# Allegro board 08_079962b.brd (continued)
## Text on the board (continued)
Ref Des/Silkscreen Bottom: A | C | SECONDARY SIDE | 08-079962 REV B | BUCK-BOOST WITH iSHARE
User.Comments: HEATSINK | DETAIL B | DETAIL A | SEE NOTE 7 (4 PLACES) | DETAIL C | DETAIL D | WITH LEAD-FREE AND RoHS PCB ASSEMBLY STANDARDS | (EU RoHS DIRECTIVE 2002/95/EC). | 7.    INSTALL STANDOFF: M048748 (MFG PN: 8834) ON FOUR CORNER HOLES OF THE BOARD. | 8.    INSTALL RING LUG: M048369 (MFG PN: 8205), WASHER: M000140 (MFG PN:  98438A230), | 4.    RoHS COMPLIANCE NOTE: ASSEMBLY VENDOR SHOULD ASSURE COMPLIANCE | 5.    SMOOTHEN EDGES AND FREE FROM BURRS AFTER DEPANELIZATION PROCESS. | 6.    INSTALL SHUNT: M022926 (MFG PN: 2SN-BK-G) ON PIN 1 AND PIN 2 OF JP1. | SEE DETAIL B. | AND NUTS: M069690 (MFG PN: 92671A195) ON J1-J4. SEE DETAIL D.
Ref Des/Assembly Top: A | C
Ref Des/Silkscreen Top: A | C | 08-079962 REV B | PRIMARY SIDE | PARALLEL SYNCRONOUS | FEATURING GaN FETS | EVAL-LT8292-AZ | BUCK-BOOST WITH iSHARE | PARALLEL SYNCHRONOUS | FEATURING GaN FETs | EVAL-LT8292-GZ
PAGE_OUTLINE: FAB NOTES REVISION: 2ND NOVEMBER 2022 | 8.   IMPEDANCE REQUIREMENTS: IF NO STACKUP IS DEFINED, THE VENDOR IS ALLOWED TO ADJUST THE DIELECTRIC | 13.  PLATING SPECIFICATION: | 9.   FILLET OPTIONS TO ENHANCE RELIABILITY AT PAD JUNCTIONS WHERE SPACING PERMITS. | 10.  THIEVING: | 11.  LAYER TO LAYER REGISTRATION SHALL BE WITHIN 0.003 INCHES. | 12.  DRILL SIZES ARE FINISHED HOLE SIZES. ALL HOLES SHALL BE LOCATED WITHIN 0.005 INCHES DTP,UNLESS SPECIFIED. | 14.  SURFACE FINISH: | 15.  SOLDERMASK: | 1.   DIMENSIONS ARE IN INCHES (EXCEPT WHERE NOTED). | ALL DOCUMENTS & SPECIFICATIONS REFERRED TO BELOW SHOULD BE THE LATEST REVISIONS. | 2.  BOARD MATERIAL:(USE CHECKED ITEMS) | 3.   ALL LAMINATES & BONDING MATERIALS SHOULD BE SELECTED FROM IPC-4101 OR IPC-4103,(TG>170 DEGC TD>300 DEGC) | 4.   REFER TO IPC-6010 SERIES, CLASS 2 FOR FABRICATION. | 5.   REFER TO LAMINATION DIAGRAM FOR OVERALL BOARD THICKNESS, TOLERANCE APPLIES AFTER ALL LAMINATION AND PLATING | 6.   BOW & TWIST NOT TO EXCEED 0.0075 INCHES (0.75%) PER LINEAR INCH AND SHOULD BE MEASURED PER IPC-TM-650, METHOD 2.4.22. | 7.   ACCEPTABILITY PER ADI SPECIFICATION TST00115. | 16.  APPLY SILKSCREEN TO BOTH SIDES USING A NON-CONDUCTIVE, EPOXY BASED INK PER ARTWORK. | ( ) FILLETS ALLOWED | (X) FILLETS NOT ALLOWED | ( ) VENDOR MAY ADD THIEVING TO COMPENSATE FOR LOW COPPER DENSITY AREAS MAINTAINING A MINIMUM | (X) VENDOR MAY NOT ADD THIEVING TO COMPENSATE FOR LOW COPPER DENSITY AREAS. | (X) LPI | ( ) OTHER_________ | COLOR | ( ) GREEN | (X) OTHER_________ | (X) WHITE | HINDER PROPER SOLDER WICKING. BARREL RELIEF ON SOLDERMASK ALLOWED IN UNFILLED VIA IN PAD HOLES. | (X) REFER TO LAMINATION DIAGRAM FOR FINISHED COPPER WEIGHT/THICKNESS REQUIRMENTS | (X) IMMERSION GOLD (ENIG) 1.58-3.94 MICRO INCHES OVER 118-236 MICRO INCHES MIN. OF ELECTROLESS NICKEL PER IPC-4552 | ( ) OSP (ORGANIC SOLDERABILITY PRESERVATIVE) | ( ) IMMERSION SILVER | ( ) SOFT WIRE BONDABLE GOLD 30-50 MICRO INCHES OF SOFT WIRE | ( ) EDGE CONNECTOR FINGERS ARE TO BE PLATED WITH 100 MICRO-INCHES(.0001") OF LOW STRESS | THICKNESS & TRACE WIDTHS TO MEET THE IMPEDANCE REQUIREMENT. IF SPECIFIED, THE VENDOR MUST | TRACE WIDTH & SPACING THAT IMPACT THE REQUIREMENTS MUST HAVE WRITTEN APPROVAL FROM ADI. | MINIMUM BARREL PLATING OF 0.001 INCHES. PLATED HOLES SHALL NOT BE ROUGH OR IRREGULAR SO AS TO | SOLDERMASK OVER BARE COPPER OR BARE GOLD (BOTH SIDES) TO MEET IPC-SM-840. | IF PRESENT,DO NOT MODIFY SOLDERMASK DEFINED PADS (MASK OPENINGS LESS THAN COPPER PAD) WITHOUT APPROVAL. | MEET THE REQUIREMENTS LISTED IN THE IMPEDANCE TABLE. ANY ADJUSTMENT MADE TO THE DEFINED STACKUP, | PROCESSES. FINISHED THICKNESS MEASURED FROM TOP COPPER TO BOTTOM COPPER. | (X)  ISOLA 370HR OR S1000-2 OR IT180 OR EQUIVALENT | ( )  ISOLA-FR408HR OR EQUIVALENT | ( )  ISOLA IS410 | ( )  MEGTRON 6 | ( )  NELCO-4000-13 | ( )  ROGERS 4350B | ( ) ROGERS 3003 | ( ) ARLON 85N | ( ) EM370D | ( )  OTHER ________________________ | UL FLAMMABILITY RATING 94V-0. BOARD MATERIAL & CONSTRUCTION SHALL MEET THE REQUIREMENTS OF UL796/UL796F. | BONDABLE GOLD OVER 100-150 MICRO INCHES OF NICKEL | NICKEL UNDER 30 MICRO-INCHES (.0003') OF GOLD | 0.100 INCH CLEARANCE FROM ALL COPPER FEATURES, | THE STARTING COPPER WEIGHT/THICKNESS CAN VARY AS LONG AS THE FINISHED COPPER | WEIGHT/THICKNESS IS NOT LESS THAN THE SPECIFIED VALUE. | UNLESS OTHERWISE SPECIFIED | BLUE | HOMOGENOUS MATERIALS IN THIS BOARD SHALL BE COMPLAINT WITH THE EU DIRECTIVE 2002/95/EC | WORKMANSHIP SHALL CONFORM TO IPC-A-600, CLASS 2. | 21.  INTENTIONAL SHORTS: | 17.  FINAL ELECTRICAL TEST TO BE PERFORMED USING PROVIDED IPC-D-356A NETLIST OR ODB++ FORMAT FILE. | 22.  PEMNUTS: | 23.  MANUFACTURER TO ETCH/STAMP WITH PERMANENT NON-CONDUCTIVE INK | ON SECONDARY SIDE UNLESS OTHERWISE SPECIFIED: | 18.  A TIME DOMAIN REFLECTOMETER REPORT (TDR) FOR EACH IMPEDANCE CONTROLLED LAYER & A CERTIFICATE | 19.  IF PRESENT, ALL BLIND/BURIED VIAS WITH AN ASPECT RATIO <1:1 TO BE PLATED SHUT WITH COPPER WHEN | 20.  FOR VIA FILL INFORMATION REFER TO DRILL CHART: | 25. PANELIZATION: | 27.  MINIMUM DESIGN LINE WIDTH IS .010 INCH. | 28.  MINIMUM DESIGN LINE SPACING IS .005 INCH. | IS ACCEPTABLE, ALL OTHER INSTANCES MUST BE REPORTED. | IF AN INTENTIONAL SHORT REPORT IS SUPPLIED AND DOES NOT MATCH THE FAB DATA THEN | THE PCB SHALL HAVE A VERIFICATION STAMP. | (X)  NON-CONDUCTIVE EPOXY FILL ALL DRILLED VIAS | ( )  COPPER FILL ALL 0.XXXX INCHES DRILLED VIAS | ( ) PEMNUTS TO BE INSTALLED BY FABRICATOR | ( ) PEMNUTS NOT TO BE INSTALLED BY FABRICATOR | (X) NOT APPLICABLE | USED AS VIA-IN-PAD OR AS A STACKED VIA. BLIND/BURIED VIAS WITH AN ASPECT RATIO >1:1 TO BE FILLED | A. UL CODE-FLAMMABILITY RATING FOR THOSE APPROVED MATERIALS(IF APPLICABLE) | B. DATE CODE | C. LOT NUMBER | D. MANUFACTURER LOGO | BOARDS TO BE SHIPPED IN ARRAY AND KEPT INTACT | PANEL TO BE SUBJECTED TO CUSTOMERS APPROVAL | PANEL SOLDER PASTE STENCIL GERBER TO BE PROVIDED TO ANALOG | CAN'T BE PERFORMED BECAUSE THE TRACE LENGTH IS TOO SHORT ON THE OUTER LAYERS AT THE PIN ESCAPES | ADI APPROVAL IS REQUIRED. | OF COMPLIANCE SHALL BE PROVIDED BY VENDOR AT TIME OF SHIPMENT. INSTANCES WHERE TDR TESTING | WITH NON-CONDUCTIVE EPOXY. | 0.0128 | B | PER ECR-126203 | 04JUL25 | S. DAS | TOOLING: | FINISH: | NOTES: | MATERIAL: | TESTING: | MISCELLANEOUS: | 6-LAYER STACK-UP | CUSTOMER EVALUATION
DIMENSION: - | " " | (REF) | DIA MAX | SEE NOTE 20
User.24: IN | SUPPLY | POWER | PGOOD2 | PGOOD1 | OUT | LOAD | V | I | - | +
User.45: FIGURE | SIZE | 6.0 | 10.0 | 12.0 | 40.0 | 70.0 | 100.0 | 200.0 | 213.0 | 118.0 | 187.0 | PLATED | NON-PLATED | DRILL CHART: TOP to BOTTOM | ALL UNITS ARE IN MILS | QTY | 268 | 1157 | 114 | 3 | 18 | 4 | 8 | TOLERANCE/NOTES
